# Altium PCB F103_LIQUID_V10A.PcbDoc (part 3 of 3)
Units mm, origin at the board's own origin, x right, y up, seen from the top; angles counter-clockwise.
Board outline 150.1 x 90.1 mm, 2 copper layers (TOP, BOTTOM), stack 1.6 mm thick; 78 components, 80 nets, 341 pads, 418 vias.
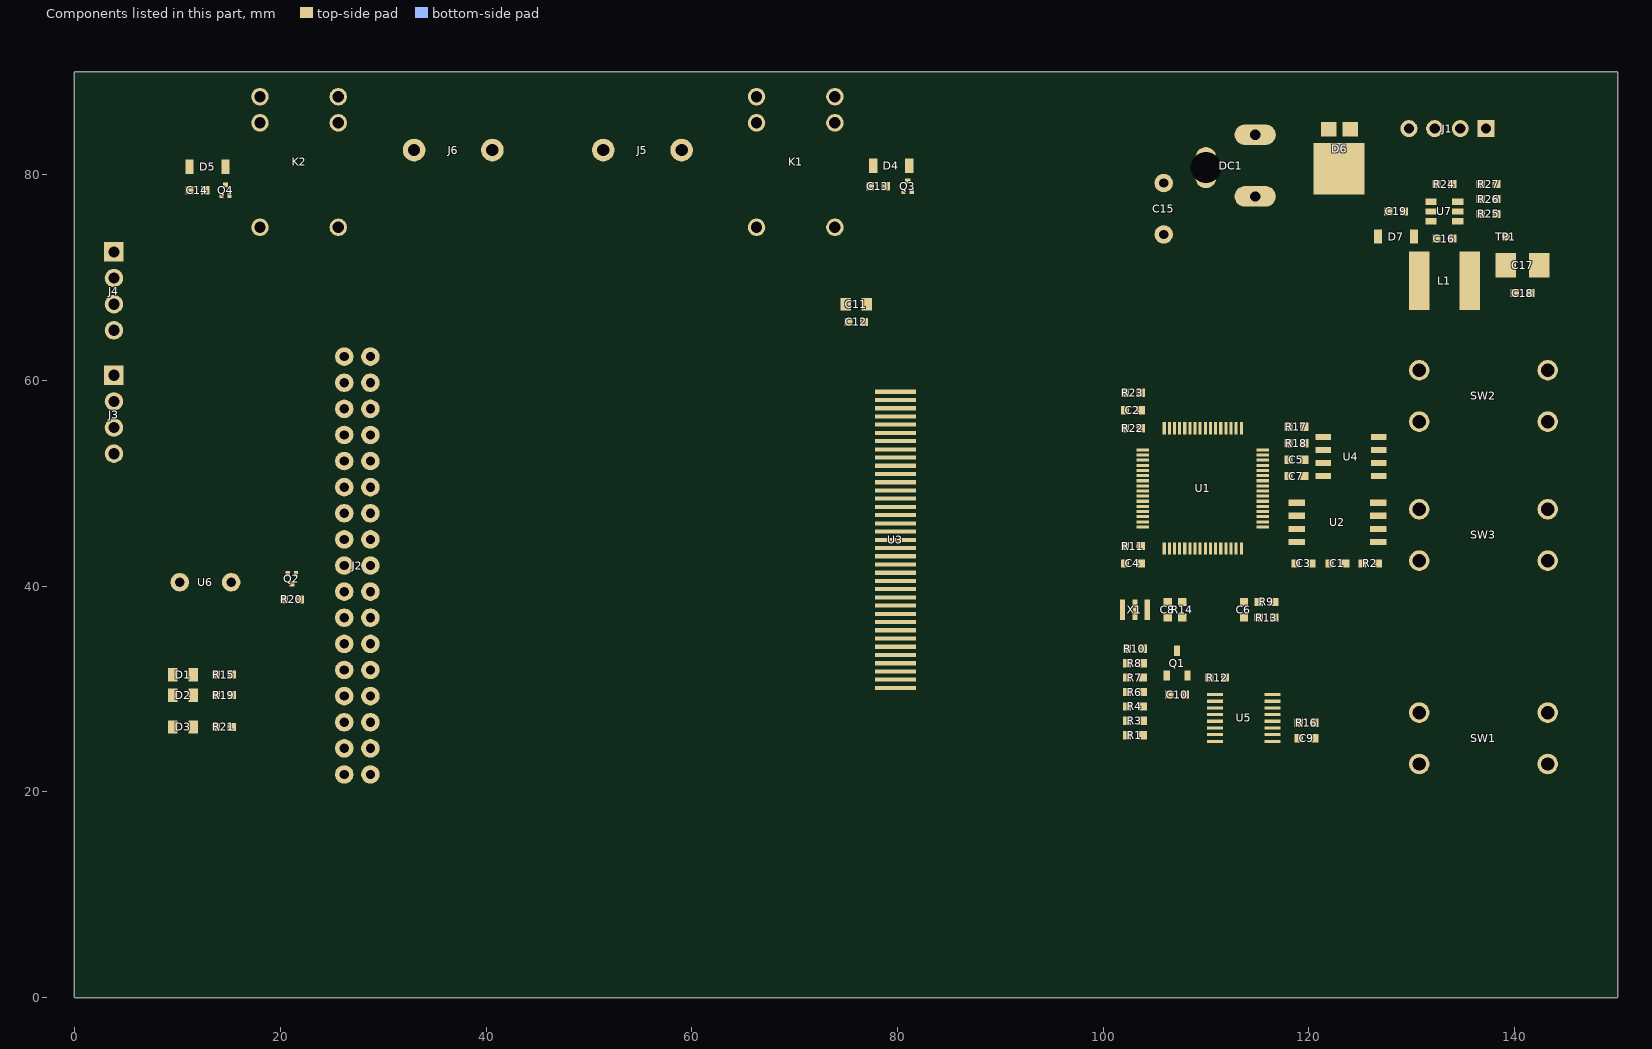
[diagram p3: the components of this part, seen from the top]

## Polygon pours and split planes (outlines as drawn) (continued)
LCD_D2 on BOTTOM "BOTTOM-LCD_D2 1" (solid, pour order 57): 26 vertices, not listed, extent 75.611,31.487 76.025,31.918
LCD_D2 on BOTTOM "BOTTOM-LCD_D2 2" (solid, pour order 20): 26 vertices, not listed, extent 109.911,48.711 110.325,49.142
LCD_D2 on BOTTOM "BOTTOM-LCD_D2 3" (solid, pour order 86): 25 vertices, not listed, extent 89.475,31.487 89.889,31.918
LCD_D4 on BOTTOM "BOTTOM-LCD_D4" (solid, pour order 83): 25 vertices, not listed, extent 90.385,46.877 90.816,47.291
LCD_D4 on BOTTOM "BOTTOM-LCD_D4 1" (solid, pour order 37): 26 vertices, not listed, extent 90.385,50.311 90.816,50.725
LCD_D3 on BOTTOM "BOTTOM-LCD_D3" (solid, pour order 326): 25 vertices, not listed, extent 28.715,31.206 29.971,32.478
LCD_D3 on BOTTOM "BOTTOM-LCD_D3 1" (solid, pour order 98): 26 vertices, not listed, extent 75.611,32.286 76.025,32.718
LCD_D3 on BOTTOM "BOTTOM-LCD_D3 2" (solid, pour order 49): 25 vertices, not listed, extent 105.311,49.485 105.725,49.916
LCD_D3 on BOTTOM "BOTTOM-LCD_D3 3" (solid, pour order 97): 26 vertices, not listed, extent 89.473,32.286 89.887,32.718
T_CS on BOTTOM "BOTTOM-T_CS" (solid, pour order 340): 25 vertices, not listed, extent 27.84,61.422 28.758,62.34
T_CS on BOTTOM "BOTTOM-T_CS 1" (solid, pour order 106): 25 vertices, not listed, extent 106.432,45.795 106.755,46.118
T_SCK on BOTTOM "BOTTOM-T_SCK" (solid, pour order 327): 25 vertices, not listed, extent 24.969,61.686 26.225,62.958
T_SCK on BOTTOM "BOTTOM-T_SCK 1" (solid, pour order 51): 25 vertices, not listed, extent 109.235,45.711 109.666,46.125
T_PEN on BOTTOM "BOTTOM-T_PEN" (solid, pour order 354): 26 vertices, not listed, extent 28.715,59.141 30.011,60.418
T_PEN on BOTTOM "BOTTOM-T_PEN 1" (solid, pour order 46): 25 vertices, not listed, extent 109.971,45.711 110.402,46.125
T_MISO on BOTTOM "BOTTOM-T_MISO" (solid, pour order 319): 25 vertices, not listed, extent 28.715,56.606 29.971,57.878
T_MISO on BOTTOM "BOTTOM-T_MISO 1" (solid, pour order 48): 25 vertices, not listed, extent 110.708,45.711 111.139,46.125
T_MOSI on BOTTOM "BOTTOM-T_MOSI" (solid, pour order 328): 25 vertices, not listed, extent 26.182,56.342 27.1,57.26
T_MOSI on BOTTOM "BOTTOM-T_MOSI 1" (solid, pour order 47): 25 vertices, not listed, extent 111.444,45.711 111.875,46.125
CTL_RELAY2 on BOTTOM "BOTTOM-CTL_RELAY2" (solid, pour order 85): 25 vertices, not listed, extent 14.085,76.811 14.516,77.225
CTL_RELAY2 on BOTTOM "BOTTOM-CTL_RELAY2 1" (solid, pour order 18): 25 vertices, not listed, extent 113.584,47.675 114.015,48.089

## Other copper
TOP:
  pour cut-out: 0,0 0.254,0 0.254,0.254 0,0.254
  pour cut-out: 0,0 0.254,0 0.254,0.254 0,0.254
  pour cut-out: 0,0 0.254,0 0.254,0.254 0,0.254
  pour cut-out: 0,0 0.254,0 0.254,0.254 0,0.254
  pour cut-out: 0,0 0.254,0 0.254,0.254 0,0.254
  pour cut-out: 0,0 0.254,0 0.254,0.254 0,0.254
  pour cut-out: 0,0 0.254,0 0.254,0.254 0,0.254
  pour cut-out: 0,0 0.254,0 0.254,0.254 0,0.254
  pour cut-out: 0,0 0.254,0 0.254,0.254 0,0.254
  pour cut-out: 0,0 0.254,0 0.254,0.254 0,0.254
  pour cut-out: 0,0 0.254,0 0.254,0.254 0,0.254
  pour cut-out: 0,0 0.254,0 0.254,0.254 0,0.254
  pour cut-out: 0,0 0.254,0 0.254,0.254 0,0.254
  pour cut-out: 0,0 0.254,0 0.254,0.254 0,0.254
  pour cut-out: 0,0 0.254,0 0.254,0.254 0,0.254
  pour cut-out: 0,0 0.254,0 0.254,0.254 0,0.254
  pour cut-out: 0,0 0.254,0 0.254,0.254 0,0.254
  pour cut-out: 0,0 0.254,0 0.254,0.254 0,0.254
  pour cut-out: 0,0 0.254,0 0.254,0.254 0,0.254
  pour cut-out: 0,0 0.254,0 0.254,0.254 0,0.254
  pour cut-out: 0,0 0.254,0 0.254,0.254 0,0.254
  pour cut-out: 0,0 0.254,0 0.254,0.254 0,0.254
  pour cut-out: 0,0 0.254,0 0.254,0.254 0,0.254
  pour cut-out: 0,0 0.254,0 0.254,0.254 0,0.254
  pour cut-out: 0,0 0.254,0 0.254,0.254 0,0.254
  pour cut-out: 0,0 0.254,0 0.254,0.254 0,0.254
  pour cut-out: 0,0 0.254,0 0.254,0.254 0,0.254
  pour cut-out: 0,0 0.254,0 0.254,0.254 0,0.254
  pour cut-out: 0,0 0.254,0 0.254,0.254 0,0.254
  pour cut-out: 0,0 0.254,0 0.254,0.254 0,0.254
  pour cut-out: 0,0 0.254,0 0.254,0.254 0,0.254
  pour cut-out: 138.009,54 137.974,54.261 137.874,54.504 137.713,54.713 137.504,54.874 137.261,54.974 137,55.009 136.739,54.974 136.496,54.874 136.287,54.713 136.126,54.504 136.026,54.261 135.991,54 136.026,53.739 136.126,53.496 136.287,53.287 136.496,53.126 136.739,53.026 137,52.991 137.261,53.026 137.504,53.126 137.713,53.287 137.874,53.496 137.974,53.739 138.009,54
  pour cut-out: 138.009,49.474 137.974,49.735 137.874,49.978 137.713,50.187 137.504,50.347 137.261,50.448 137,50.482 136.739,50.448 136.496,50.347 136.287,50.187 136.126,49.978 136.026,49.735 135.991,49.474 136.026,49.212 136.126,48.969 136.287,48.76 136.496,48.6 136.739,48.499 137,48.465 137.261,48.499 137.504,48.6 137.713,48.76 137.874,48.969 137.974,49.212 138.009,49.474
  pour cut-out: 138.009,40.474 137.974,40.735 137.874,40.978 137.713,41.187 137.504,41.347 137.261,41.448 137,41.482 136.739,41.448 136.496,41.347 136.287,41.187 136.126,40.978 136.026,40.735 135.991,40.474 136.026,40.212 136.126,39.969 136.287,39.76 136.496,39.6 136.739,39.499 137,39.465 137.261,39.499 137.504,39.6 137.713,39.76 137.874,39.969 137.974,40.212 138.009,40.474
  pour cut-out: 119.43,66.122 119.382,66.616 119.238,67.09 119.004,67.528 118.689,67.911 118.306,68.226 117.868,68.46 117.394,68.604 116.9,68.652 116.406,68.604 115.932,68.46 115.494,68.226 115.111,67.911 114.796,67.528 114.562,67.09 114.418,66.616 114.37,66.122 114.418,65.628 114.562,65.154 114.796,64.716 115.111,64.333 115.494,64.018 115.932,63.784 116.406,63.64 116.9,63.592 117.394,63.64 117.868,63.784 118.306,64.018 118.689,64.333 119.004,64.716 119.238,65.154 119.382,65.628 119.43,66.122
  pour cut-out: 0,0 0.254,0 0.254,0.254 0,0.254
  pour cut-out: 0,0 0.254,0 0.254,0.254 0,0.254
  pour cut-out: 0,0 0.254,0 0.254,0.254 0,0.254
  pour cut-out: 0,0 0.254,0 0.254,0.254 0,0.254
  pour cut-out: 144.765,27.7 144.736,27.996 144.65,28.28 144.51,28.542 144.322,28.772 144.092,28.96 143.83,29.1 143.546,29.186 143.25,29.215 142.954,29.186 142.67,29.1 142.408,28.96 142.178,28.772 141.99,28.542 141.85,28.28 141.764,27.996 141.735,27.7 141.764,27.404 141.85,27.12 141.99,26.858 142.178,26.628 142.408,26.44 142.67,26.3 142.954,26.214 143.25,26.185 143.546,26.214 143.83,26.3 144.092,26.44 144.322,26.628 144.51,26.858 144.65,27.12 144.736,27.404 144.765,27.7
  pour cut-out: 132.265,27.7 132.236,27.996 132.15,28.28 132.01,28.542 131.822,28.772 131.592,28.96 131.33,29.1 131.046,29.186 130.75,29.215 130.454,29.186 130.17,29.1 129.908,28.96 129.678,28.772 129.49,28.542 129.35,28.28 129.264,27.996 129.235,27.7 129.264,27.404 129.35,27.12 129.49,26.858 129.678,26.628 129.908,26.44 130.17,26.3 130.454,26.214 130.75,26.185 131.046,26.214 131.33,26.3 131.592,26.44 131.822,26.628 132.01,26.858 132.15,27.12 132.236,27.404 132.265,27.7
  pour cut-out: 138.009,29.7 137.974,29.961 137.874,30.204 137.713,30.413 137.504,30.574 137.261,30.674 137,30.709 136.739,30.674 136.496,30.574 136.287,30.413 136.126,30.204 136.026,29.961 135.991,29.7 136.026,29.439 136.126,29.196 136.287,28.987 136.496,28.826 136.739,28.726 137,28.691 137.261,28.726 137.504,28.826 137.713,28.987 137.874,29.196 137.974,29.439 138.009,29.7
  pour cut-out: 138.009,20.7 137.974,20.961 137.874,21.204 137.713,21.413 137.504,21.574 137.261,21.674 137,21.709 136.739,21.674 136.496,21.574 136.287,21.413 136.126,21.204 136.026,20.961 135.991,20.7 136.026,20.439 136.126,20.196 136.287,19.987 136.496,19.826 136.739,19.726 137,19.691 137.261,19.726 137.504,19.826 137.713,19.987 137.874,20.196 137.974,20.439 138.009,20.7
  pour cut-out: 119.33,17.522 119.282,18.016 119.138,18.49 118.904,18.928 118.589,19.311 118.206,19.626 117.768,19.86 117.294,20.004 116.8,20.052 116.306,20.004 115.832,19.86 115.394,19.626 115.011,19.311 114.696,18.928 114.462,18.49 114.318,18.016 114.27,17.522 114.318,17.028 114.462,16.554 114.696,16.116 115.011,15.733 115.394,15.418 115.832,15.184 116.306,15.04 116.8,14.992 117.294,15.04 117.768,15.184 118.206,15.418 118.589,15.733 118.904,16.116 119.138,16.554 119.282,17.028 119.33,17.522
  pour cut-out: 105.83,19.622 105.782,20.116 105.638,20.59 105.404,21.028 105.089,21.411 104.706,21.726 104.268,21.96 103.794,22.104 103.3,22.152 102.806,22.104 102.332,21.96 101.894,21.726 101.511,21.411 101.196,21.028 100.962,20.59 100.818,20.116 100.77,19.622 100.818,19.128 100.962,18.654 101.196,18.216 101.511,17.833 101.894,17.518 102.332,17.284 102.806,17.14 103.3,17.092 103.794,17.14 104.268,17.284 104.706,17.518 105.089,17.833 105.404,18.216 105.638,18.654 105.782,19.128 105.83,19.622
BOTTOM:
  drawing of 236 lines, arcs and shapes, not listed

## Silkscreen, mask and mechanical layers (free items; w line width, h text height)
CUTOUT:
  lines w0.1: 0,0 150,0 150,90 0,90 0,0
DIMENSION:
  lines w0.025: -30.3,0 -2.5,0 ; -30.3,90 -2.2,90 ; -27.8,33.943 -27.8,0 ; -27.8,38.857 -27.8,90 ; -24,0 -2.5,0 ; -24,86.8 0.7,86.8 ; -21.5,28.143 -21.5,0 ; -21.5,33.057 -21.5,86.8 ; -17.2,0 -2.5,0 ; -17.2,80.5 0.7,80.5 ; -14.7,21.043 -14.7,0 ; -14.7,25.957 -14.7,80.5 ; -13.7,0 -2.5,0 ; -13.7,9.5 0.7,9.5 ; -11.2,11.243 -11.2,9.5 ; -8.2,0 -2.5,0 ; -8.2,3.2 0.7,3.2 ; -8,-2.8 0,-2.8 ; -5.7,-8 -5.7,0 ; -5.7,5.843 -5.7,3.2 ; 0,-19.9 0,-2.5 ; 0,-15.2 0,-2.5 ; 0,-11.9 0,-2.5 ; 0,-8.1 0,-2.5 ; 0,-5.3 0,-2.5 ; 3.2,-5.3 3.2,0.7 ; 7.779,-2.8 3.2,-2.8 ; 18.031,-5.6 0,-5.6 ; 24.126,-9.4 0,-9.4 ; 24.369,-5.6 75,-5.6 ; 34.274,-9.4 91.5,-9.4 ; 45.374,-12.7 0,-12.7 ; 56.379,-17.4 0,-17.4 ; 57.426,-12.7 146.8,-12.7 ; 64.621,-17.4 150,-17.4 ; 75,-8.1 75,0.7 ; 91.5,-11.9 91.5,84.3 ; 146.8,-15.2 146.8,0.7 ; 150,-19.9 150,-2.5 ; -27.8,0 -27.175,4 -28.425,4 -27.8,0 ; -27.8,90 -28.425,86 -27.175,86 -27.8,90 ; -21.5,0 -20.875,4 -22.125,4 -21.5,0 ; -21.5,86.8 -22.125,82.8 -20.875,82.8 -21.5,86.8 ; -14.7,0 -14.075,4 -15.325,4 -14.7,0 ; -14.7,80.5 -15.325,76.5 -14.075,76.5 -14.7,80.5 ; -11.2,0 -11.2,9.5 ; -11.2,0 -10.575,4 -11.825,4 -11.2,0 ; -11.2,9.5 -11.825,5.5 -10.575,5.5 -11.2,9.5 ; -5.7,0 -6.325,-4 -5.075,-4 -5.7,0 ; -5.7,3.2 -5.075,7.2 -6.325,7.2 -5.7,3.2 ; 0,-17.4 4,-18.025 4,-16.775 0,-17.4 ; 0,-12.7 4,-13.325 4,-12.075 0,-12.7 ; 0,-9.4 4,-10.025 4,-8.775 0,-9.4 ; 0,-5.6 4,-6.225 4,-4.975 0,-5.6 ; 0,-2.8 -4,-2.175 -4,-3.425 0,-2.8 ; 3.2,-2.8 7.2,-3.425 7.2,-2.175 3.2,-2.8 ; 75,-5.6 71,-4.975 71,-6.225 75,-5.6 ; 91.5,-9.4 87.5,-8.775 87.5,-10.025 91.5,-9.4 ; 146.8,-12.7 142.8,-12.075 142.8,-13.325 146.8,-12.7 ; 150,-17.4 146,-16.775 146,-18.025 150,-17.4
  text "90" at -29.464,35.448 h1.91
  text "86.8" at -25.069,29.647 h1.91
  text "80.5" at -18.269,22.548 h1.91
  text "9.5" at -13.816,12.748 h1.91
  text "3.2" at -8.316,7.348 h1.91
  text "3.2" at 9.284,-3.752 h1.91
  text "75" at 19.536,-6.552 h1.91
  text "91.5" at 25.631,-10.352 h1.91
  text "146.8" at 46.879,-13.652 h1.91
  text "150" at 57.884,-18.353 h1.91
PHOTOPLOT_OUTLINE:
  lines w0.025: -115.9,-86.525 -115.9,535.14 791.515,535.14 791.515,-86.525 -115.9,-86.525
NCLEGEND-1-2:
  lines w0.025: 161.2,7.25 319.467,7.25 ; 161.2,13.6 319.467,13.6 ; 161.2,19.95 319.467,19.95 ; 161.2,26.3 319.467,26.3 ; 161.2,32.65 319.467,32.65 ; 161.2,39 319.467,39 ; 161.2,45.35 319.467,45.35 ; 161.2,51.7 319.467,51.7 ; 161.2,58.05 319.467,58.05 ; 161.2,64.4 319.467,64.4 ; 172.465,48.525 172.77,48.525 ; 172.617,48.373 172.617,48.677 ; 184.035,0.9 184.035,58.05 ; 235.216,0.9 235.216,58.05 ; 267.499,0.9 267.499,58.05 ; 299.782,0.9 299.782,58.05 ; 161.2,0.9 161.2,70.9 319.467,70.9 319.467,0.9 161.2,0.9 ; 171.427,29.475 171.775,28.633 172.617,28.284 173.459,28.633 173.808,29.475 173.459,30.317 172.617,30.666 171.775,30.317 171.427,29.475 ; 171.617,3.075 ccw(c171.617,4.075) 171.617,5.075 173.617,5.075 ccw(c173.617,4.075) 173.617,3.075 171.617,3.075 ; 171.617,9.425 ccw(c171.617,10.425) 171.617,11.425 173.617,11.425 ccw(c173.617,10.425) 173.617,9.425 171.617,9.425 ; 172.017,22.525 172.617,23.725 173.217,22.525 172.017,22.525 ; 172.117,35.825 172.367,35.325 172.867,35.325 173.117,35.825 172.867,36.325 172.367,36.325 172.117,35.825 ; 172.167,41.725 173.067,41.725 173.067,42.625 172.167,42.625 172.167,41.725 ; 172.455,15.8 ccw(c172.455,16.775) 172.455,17.75 172.78,17.75 ccw(c172.78,16.775) 172.78,15.8 172.455,15.8
  text "DRILL CHART: TOP to BOTTOM" at 207.314,66.138 h3.17
  text "ALL UNITS ARE IN MILLIMETERS" at 204.774,59.638 h3.17
  text "FIGURE" at 164.997,53.288 h3.17
  text "FINISHED_SIZE" at 193.115,53.288 h3.17
  text "ROTATION" at 241.197,53.288 h3.17
  text "PLATED" at 276.021,53.288 h3.17
  text "QTY" at 305.815,53.288 h3.17
  text "0.3048" at 202.005,46.938 h3.17
  text "-" at 250.087,46.938 h3.17
  text "PLATED" at 276.021,46.938 h3.17
  text "418" at 305.815,46.938 h3.17
  text "0.9" at 205.815,40.588 h3.17
  text "-" at 250.087,40.588 h3.17
  text "PLATED" at 276.021,40.588 h3.17
  text "38" at 307.085,40.588 h3.17
  text "1.0" at 205.815,34.238 h3.17
  text "-" at 250.087,34.238 h3.17
  text "PLATED" at 276.021,34.238 h3.17
  text "4" at 308.355,34.238 h3.17
  text "1.1" at 205.815,27.888 h3.17
  text "-" at 250.087,27.888 h3.17
  text "PLATED" at 276.021,27.888 h3.17
  text "20" at 307.085,27.888 h3.17
  text "1.2" at 205.815,21.538 h3.17
  text "-" at 250.087,21.538 h3.17
  text "PLATED" at 276.021,21.538 h3.17
  text "4" at 308.355,21.538 h3.17
  text "1.3" at 205.815,15.188 h3.17
  text "-" at 250.087,15.188 h3.17
  text "PLATED" at 276.021,15.188 h3.17
  text "12" at 307.085,15.188 h3.17
  text "3.0x1.0" at 200.735,8.838 h3.17
  text "90.000" at 243.737,8.838 h3.17
  text "PLATED" at 276.021,8.838 h3.17
  text "1" at 308.355,8.838 h3.17
  text "3.0x1.0" at 200.735,2.488 h3.17
  text "0.000" at 245.007,2.488 h3.17
  text "PLATED" at 276.021,2.488 h3.17
  text "2" at 308.355,2.488 h3.17
  text "TOTAL HOLES:" at 266.127,-3.862 h3.17
  text "499" at 305.815,-3.862 h3.17
DETAILS:
  drawing of 2649 lines, arcs and shapes, not listed
  text "V10A" at 581.457,472.275 h2.54
  text "XXXLZJXXX" at 725.602,472.148 h2.54
  text "19-02-15" at 699.821,472.021 h2.54
  text "DETAIL A" at -27.254,437.919 h3.17
  text "1. THIS DRAWING SPECIFIES THE REQUIREMENTS FOR A" at 409.753,433.982 h2.39
  text "PRINTED WIRING BOARD IN ACCORDANCE" at 518.973,433.982 h2.39
  text "LAYER STACKUP" at -33.604,430.299 h3.17
  text "WITH SPECIFICATION IPC-A-600 CLASS 2 (LATEST REVISION)." at 412.293,428.902 h2.39
  text "SCALE: NONE" at -19.888,423.949 h0.64
  text "2. THE PWB MUST BE LEAD FREE ASSEMBLY PROCESS COMPATIBLE AND MUST BE ABLE TO HANDLE" at 409.753,418.742 h2.39
  text "A MINIMUM OF 5 CYCLES AT 260 DEGREES CELSIUS FOR 10 SECONDS." at 412.293,413.662 h2.39
  text "DETAIL B" at 248.836,407.686 h3.17
  text "JLC:  1.6mm THK +/- 10%" at -52.654,405.534 h3.17
  text "FINISHED Cu WEIGHT" at 83.998,404.01 h3.17
  text "3. BASE MATERIAL - LAMINATE AND PREPREG SHALL MEET IPC-4101B-26, 83 or 98" at 409.753,403.502 h2.39
  text "IMPEDANCE REQUIREMENTS" at 231.463,402.302 h3.17
  text "IMPEDANCE TOLERANCE IS 10%" at 226.383,397.222 h3.17
  text "Tg - MUST BE GREATER THAN OR EQUAL TO 150 DEGREES CELSIUS." at 409.753,393.342 h2.39
  text "LAYER 1  TOP SIDE          1oz+plating" at 31.166,389.024 h3.17
  text "Td - MUST BE GREATER THAN OR EQUAL TO 330 DEGREES CELSIUS." at 409.753,388.262 h2.39
  text "Single Ended" at 215.912,387.849 h0.51
  text "Differential" at 267.054,387.756 h0.51
  text "Differential" at 329.799,387.756 h0.51
  text "Impedance" at 295.033,382.744 h1.6
  text "Impedance" at 357.777,382.744 h1.6
  text "Impedance" at 233.311,382.617 h1.6
  text "Layers" at 191.68,382.566 h0.51
  text "Trace Spacing" at 271.69,382.566 h1.6
  text "Trace Spacing" at 334.435,382.566 h1.6
  text "Trace Width" at 212.102,382.363 h1.6
  text "Trace Width" at 251.726,382.363 h1.6
  text "Trace Width" at 314.47,382.363 h1.6
  text "(Mils)" at 213.27,380.026 h1.6
  text "(Ohms)" at 233.59,380.026 h1.6
  text "(Mils)" at 252.64,380.026 h1.6
  text "\"Airgap\"" at 271.69,380.026 h1.6
  text "(Ohms)" at 295.82,380.026 h1.6
  text "(Mils)" at 315.385,380.026 h1.6
  text "\"Airgap\"" at 334.435,380.026 h1.6
  text "(Ohms)" at 358.565,380.026 h1.6
  text "A_TARGET:1.53 mm" at -18.745,378.99 h1.6
  text "4. COPPER FOIL WEIGHT - SEE STACKUP DETAIL 'A'" at 409.753,378.102 h2.39
  text "(Mils)" at 276.465,377.105 h1.6
  text "(Mils)" at 339.21,377.105 h1.6
  text "L1" at 191.655,372.33 h0.9
  text "4.2" at 257.187,372.076 h0.9
  text "4.70" at 319.931,372.076 h0.9
  text "5.00" at 217.69,371.949 h0.9
  text "100" at 299.63,371.771 h0.9
  text "90" at 362.375,371.771 h0.9
  text "6.00" at 274.967,371.695 h0.9
  text "5.00" at 337.711,371.695 h0.9
  text "50" at 240.55,371.568 h0.9
  text "5. CHARACTERISTIC IMPEDANCE - SEE DETAIL 'B'" at 409.753,367.942 h2.39
  text "L4" at 191.655,367.25 h0.9
  text "4.70" at 319.931,366.996 h0.9
  text "5.00" at 217.69,366.869 h0.9
  text "90" at 362.375,366.691 h0.9
  text "5.00" at 337.711,366.615 h0.9
  text "50" at 240.55,366.488 h0.9
  text "LAYER 2  BOTTOM SIDE       1oz+plating" at 31.166,366.164 h3.17
  text "6. MINIMUM CONDUCTIVE WIDTH/SPACING TO BE .00X\"/.00X\"" at 409.753,359.052 h2.39
  text "7. PLATING FINISH - BOTH SIDES ENIG (ELECTROLESS NICKEL IMMERSION GOLD):" at 409.753,348.892 h2.39
  text ".05080-.232 MICRON (2-8 MICROINCH) OF GOLD OVER" at 456.387,343.761 h2.39
  text "2.540-6.350 MICRON (100-250 MICROINCH) OF NICKEL." at 449.479,338.757 h2.39
  text "If the angle of PCB board outline is right angle,please use this kind of break out area" at 581.33,336.7 h0.79
  text "If not use it,please delete it before you gerber out" at 581.33,331.62 h0.79
  text "8. ALL THROUGH HOLE VIAS MAY BE PLATED SHUT." at 409.753,328.572 h2.39
  text "9. SOLDERMASK - GREEN COLOR (TAIYO OR EQUIVALENT), BOTH SIDES." at 410.49,319.022 h2.39
  text "MODIFICATION OF SOLDERMASK IS NOT ALLOWED WITHOUT WRITTEN PERMISSION FROM FREESCALE." at 410.515,313.332 h2.39
  text "If the angle of PCB board outline is circular,please use this kind of break out area" at 580.06,308.76 h0.79
  text "If not use it,please delete it before you gerber out" at 580.06,304.95 h0.79
  text "10. SILKSCREEN - WHITE EPOXY INK, BOTH SIDES.  NO SILK ON PADS." at 410.49,303.782 h2.39
  text "11. ELECTRICAL TEST - 100% IPCD356." at 410.49,293.622 h2.39
  text "12. PRINTED WIRING BOARD IS TO BE INDIVIDUALLY BAGGED." at 410.49,283.462 h2.39
  text "If not use it,please delete it before you gerber out" at 581.33,275.74 h0.79
  text "13. DRC'S MUST BE RUN ON THE GERBER BEFORE BUILDING BOARDS," at 410.49,273.302 h2.39
  text "UNLESS PRIOR APPROVAL IS GIVEN IN WRITING BY FREESCALE." at 410.49,268.222 h2.39
  text "AS usual,please use the 0.8MM stamp Via" at 581.33,268.12 h0.79
  text "14. ADD TEARDROPS TO ALL SIGNAL LAYERS." at 410.49,258.062 h2.39
  text "15. SOLDER SAMPLES TO BE PROVIDED." at 410.49,247.902 h2.39
  text "16. BASIC GRID INCREMENT AT 1:1 IS .0001." at 410.49,237.742 h2.39
  text "17. SUPPLIER MARKINGS - ON SOLDER SIDE ONLY, WHERE SHOWN." at 410.49,225.042 h2.39
  text "- MUST BE UL RECOGNIZED AND MUST HAVE AN ID THAT CONFORMS TO UL94V-0" at 409.753,219.352 h2.39
  text "If not use it,please delete it before you gerber out" at 605.46,213.51 h0.79
  text "18. THE PWB WILL BE MARKED AS LEAD FREE BY USE OF AN INK STAMP Pb" at 413.03,207.897 h2.39
  text "19. THE PWB WILL BE MARKED AS LEAD FREE PROCESS COMPATIBLE BY USE OF AN INK STAMP 260 C" at 413.03,200.277 h2.39
  text "20. ALL PLATED AND NON-PLATED THROUGH HOLES ARE TO BE DRILLED AT PRIMARY DRILL STEP." at 430.749,191.666 h2.39
  text "ALL HOLE LOCATION TOLERANCES ARE TO BE +/-.002 IN REFERENCE TO THE PRIMARY DATUM." at 439.71,186.967 h2.39
  text "21. FINISHED PCB MUST BE PANELIZED FOR ASSEMBLY ACCORDING TO CONTRACT MANUFACTURING REQUIREMENT." at 413.563,178.712 h2.39
  text "ADDITION OF .25\" RAILS AND .125\" NON-PLATED TOOLING HOLES ARE AT THE DISCRETION" at 422.453,174.14 h2.39
  text "OF CONTRACT MANUFACTURER AND FAB HOUSE." at 422.453,169.822 h2.39
  text "PANELIZATION MUST BE APPROVED BY FREESCALE." at 422.453,164.742 h2.39
  text "NO-*****" at 556.756,26.59 h3.17
  text "THIS DOCUMENT CONTAINS INFORMATION" at 551.485,20.79 h1.6
  text "___ PUBI (PUBLIC INFORMATION)" at 479.222,19.901 h1.6
  text "HYOC" at 616.509,17.996 h5.71
  text "PROPRIETARY TO FREESCALE AND SHALL" at 551.485,17.615 h1.6
  text "NOT BE USED FOR ENGINEERING DESIGN" at 551.485,14.44 h1.6
  text "___ FIUO (HY INTERNAL USE ONLY)" at 479.222,12.281 h1.6
  text "X" at 480.238,12.281 h2.54
  text "PROCUREMENT OR MANUFACTURE IN WHOLE" at 551.485,11.265 h1.6
  text "OR IN PART WITHOUT THE CONSENT OF" at 551.485,8.09 h1.6
  text "NXP." at 551.485,4.915 h1.6
  text "___ FCP (HY CONFIDENTIAL PROPRIETARY)" at 479.222,4.661 h1.6
  text "XXXLZJXXX" at 561.264,-11.341 h2.54
  text "DRV8711_TEST_V10A" at 653.085,-15.532 h4.44
  text "XXXLZJXXX" at 561.137,-22.009 h2.54
  text "XXXLZJXXX" at 561.01,-32.042 h2.54
  text "19_02_15" at 593.332,-32.042 h2.54
  text "CAD-*****" at 625.907,-32.55 h3.17
  text "FAB-*****" at 679.374,-32.55 h4.44
  text "A2" at 739.826,-32.55 h4.44
  text "1/1" at 625.005,-42.625 h3.17
  text "1" at 734.962,-42.647 h3.17
  text "1" at 721.881,-42.774 h3.17
DRAWING_ORIGIN:
  lines w0.025: -0.635,0 0.635,0 ; 0,-0.635 0,0.635
PANEL:
  lines w0.025: -7.874,0 -0.207,0 ; -0.207,0 -4.017,0.635 -4.017,-0.635 -0.207,0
